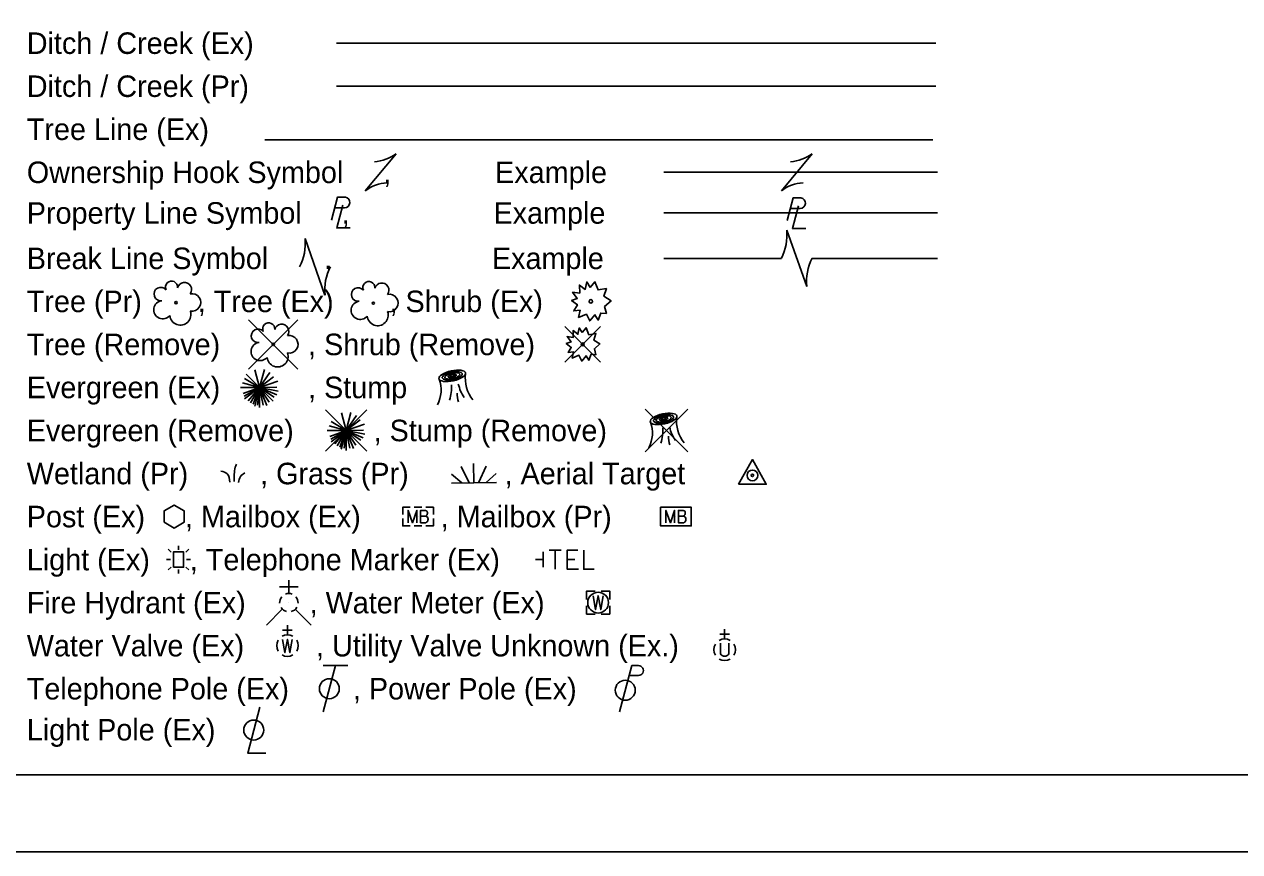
# Model space of a CAD drawing. Extents: x 0 to 34, y -5.4 to 22.
# Drawn here: x 7.96 to 15.87, y 0 to 5.38 of the extents above; entities that cross this region are included whole.
import ezdxf

# ---------------------------------------------------------------- set-up
doc = ezdxf.new("R2010")
doc.units = 0
for name, color, linetype in [('SH_Border', 7, 'Continuous'), ('SH_Cut_Line', 7, 'Continuous'), ('SH_Text', 7, 'Continuous')]:
    doc.layers.add(name, color=color, linetype=linetype)

msp = doc.modelspace()

# ---------------------------------------------------------------- linework, layer by layer
at = {"layer": 'SH_Border'}
msp.add_lwpolyline([(1.5, 21.5), (33.5, 21.5), (33.5, 0.5), (1.5, 0.5)], close=True, dxfattribs=at)
at = {"layer": 'SH_Cut_Line'}
msp.add_lwpolyline([(0, 0), (34, 0), (34, 22), (0, 22)], close=True, dxfattribs=at)
at = {"layer": 'SH_Text'}
for p, q in [((9.9949, 5.2604), (13.8949, 5.2604)), ((9.9949, 4.9804), (13.8949, 4.9804)), ((9.5272, 4.6304), (13.8772, 4.6304)), ((10.1822, 4.3004), (10.3822, 4.5404)), ((12.8904, 4.3004), (13.0904, 4.5404)), ((10.2822, 4.4204), (10.2822, 4.4204)), ((12.1249, 4.4204), (13.9072, 4.4204)), ((12.9904, 4.4204), (12.9904, 4.4204)), ((9.9825, 4.1894), (10.0473, 4.1894)), ((10.0225, 4.1583), (10.0225, 4.1583)), ((12.1249, 4.1558), (13.9072, 4.1558)), ((12.9481, 4.1853), (13.0129, 4.1853)), ((12.9882, 4.1542), (12.9882, 4.1542)), ((12.9254, 4.0446), (13.0554, 3.6764)), ((9.7898, 3.989), (9.9197, 3.6207)), ((9.8547, 3.8049), (9.8547, 3.8049)), ((12.1249, 3.8604), (12.8905, 3.8604)), ((12.9904, 3.8605), (12.9904, 3.8605)), ((13.0903, 3.8604), (13.9072, 3.8604)), ((9.4226, 3.4607), (9.7433, 3.14)), ((9.7433, 3.4607), (9.4226, 3.14)), ((11.4817, 3.4163), (11.7134, 3.1846)), ((11.7134, 3.4163), (11.4817, 3.1846)), ((9.5829, 3.3004), (9.5829, 3.3004)), ((11.5975, 3.3004), (11.5975, 3.3004)), ((9.4934, 3.0202), (9.4062, 3.1074)), ((9.4934, 3.0202), (9.4626, 3.1355)), ((9.4934, 3.0202), (9.5249, 3.1377)), ((9.4934, 3.0202), (9.5598, 3.1173)), ((9.4934, 3.0202), (9.5849, 3.0903)), ((9.3701, 3.0202), (9.4934, 3.0202)), ((9.4934, 3.0202), (9.3831, 3.0498)), ((9.4934, 3.0202), (9.3862, 2.9812)), ((9.4934, 3.0202), (9.3939, 2.9632)), ((9.4934, 3.0202), (9.3958, 3.0776)), ((9.4934, 3.0202), (9.3958, 2.9453)), ((9.4934, 3.0202), (9.4198, 2.9335)), ((9.4934, 3.0202), (9.4355, 2.9198)), ((9.4934, 3.0202), (9.4518, 2.9117)), ((9.4934, 3.0202), (9.4619, 2.8988)), ((9.4934, 3.0202), (9.4799, 2.9054)), ((9.4934, 3.0202), (9.6119, 3.0604)), ((9.4934, 3.0202), (9.6062, 3.0225)), ((9.4934, 2.8892), (9.4934, 3.0202)), ((9.4934, 3.0202), (9.5165, 2.9043)), ((9.4934, 3.0202), (9.5418, 2.9035)), ((9.4934, 3.0202), (9.5569, 2.9254)), ((9.4934, 3.0202), (9.5831, 2.9322)), ((9.4934, 3.0202), (9.589, 2.9563)), ((9.4934, 3.0202), (9.6051, 2.9717)), ((9.4934, 3.0202), (9.6141, 2.9962)), ((10.7671, 3.0204), (10.7671, 3.0204)), ((9.9238, 2.8741), (10.1911, 2.6068)), ((10.1911, 2.8741), (9.9238, 2.6068)), ((10.0575, 2.7404), (10.0266, 2.8558)), ((10.0575, 2.7404), (10.0889, 2.8579)), ((12.0036, 2.8795), (12.2817, 2.6014)), ((12.2817, 2.8795), (12.0036, 2.6014)), ((10.0575, 2.7404), (9.9471, 2.77)), ((10.0575, 2.7404), (9.9598, 2.7978)), ((10.0575, 2.7404), (9.9702, 2.8276)), ((10.0575, 2.7404), (10.1238, 2.8376)), ((10.0575, 2.7404), (10.1489, 2.8106)), ((10.0575, 2.7404), (10.1759, 2.7806)), ((9.9341, 2.7404), (10.0575, 2.7404)), ((10.0575, 2.7404), (9.9502, 2.7014)), ((10.0575, 2.7404), (9.9579, 2.6834)), ((10.0575, 2.7404), (9.9598, 2.6656)), ((10.0575, 2.7404), (9.9838, 2.6538)), ((10.0575, 2.7404), (9.9995, 2.6401)), ((10.0575, 2.7404), (10.0158, 2.6319)), ((10.0575, 2.7404), (10.0259, 2.619)), ((10.0575, 2.7404), (10.0439, 2.6256)), ((10.0575, 2.7404), (10.1702, 2.7427)), ((10.0575, 2.6094), (10.0575, 2.7404)), ((10.0575, 2.7404), (10.0805, 2.6245)), ((10.0575, 2.7404), (10.1058, 2.6237)), ((10.0575, 2.7404), (10.1209, 2.6456)), ((10.0575, 2.7404), (10.1472, 2.6524)), ((10.0575, 2.7404), (10.153, 2.6766)), ((10.0575, 2.7404), (10.1691, 2.6919)), ((10.0575, 2.7404), (10.1782, 2.7165)), ((10.0575, 2.7404), (10.0575, 2.7404)), ((12.1427, 2.7404), (12.1427, 2.7404)), ((12.1427, 2.7404), (12.1427, 2.7404)), ((10.8104, 2.3993), (10.7421, 2.4564)), ((10.8591, 2.4), (10.807, 2.5061)), ((10.8891, 2.4004), (10.8872, 2.5259)), ((10.919, 2.4009), (10.968, 2.5084)), ((10.9678, 2.4016), (11.0343, 2.4607)), ((10.7429, 2.3983), (11.0351, 2.4026)), ((10.5002, 2.2415), (10.5503, 2.2415)), ((10.5258, 2.1804), (10.5258, 2.1804)), ((12.2039, 2.1804), (12.2039, 2.1804)), ((10.5002, 2.1193), (10.5503, 2.1193)), ((8.9662, 1.9644), (8.9662, 1.991)), ((8.914, 1.9008), (8.8874, 1.9008)), ((8.9179, 1.9488), (8.8994, 1.9676)), ((8.9662, 1.9004), (8.9662, 1.9004)), ((9.0328, 1.9676), (9.0142, 1.9488)), ((9.0449, 1.9008), (9.0182, 1.9008)), ((11.3388, 1.9004), (11.289, 1.9004)), ((11.3388, 1.8504), (11.3388, 1.9504)), ((8.9179, 1.852), (8.8994, 1.8333)), ((8.9662, 1.8364), (8.9662, 1.8098)), ((9.0328, 1.8333), (9.0142, 1.852)), ((9.6842, 1.6806), (9.6842, 1.7666)), ((9.7442, 1.7236), (9.6242, 1.7236)), ((9.6843, 1.6204), (9.6843, 1.6204)), ((9.6843, 1.6204), (9.6843, 1.6204)), ((11.6978, 1.6204), (11.6978, 1.6204)), ((9.6419, 1.578), (9.5379, 1.4741)), ((9.7265, 1.578), (9.8305, 1.4741)), ((9.7069, 1.4423), (9.6433, 1.4423)), ((9.6751, 1.4104), (9.6751, 1.474)), ((12.5213, 1.384), (12.5213, 1.4475)), ((12.553, 1.4158), (12.4894, 1.4158)), ((12.4941, 1.3571), (12.4941, 1.2882)), ((12.5484, 1.3571), (12.5484, 1.2882)), ((9.6751, 1.3404), (9.6751, 1.3404)), ((12.5213, 1.314), (12.5213, 1.314)), ((9.9881, 1.2104), (9.9078, 0.9104)), ((10.0681, 1.2104), (9.9081, 1.2104)), ((11.9171, 1.2104), (11.8368, 0.9104)), ((11.9171, 1.2104), (11.9596, 1.2104)), ((11.9, 1.1467), (11.9596, 1.1467))]:
    msp.add_line(p, q, dxfattribs=at)
for points in [[(9.9615, 4.1098), (10.0005, 4.2581), (10.0522, 4.258)], [(10.0359, 4.2063), (9.9963, 4.0584), (10.0836, 4.0584)], [(12.9271, 4.1058), (12.9662, 4.254), (13.0178, 4.2539)], [(13.0015, 4.2022), (12.9619, 4.0543), (13.0493, 4.0543)], [(11.6463, 3.6709), (11.6765, 3.7077), (11.6973, 3.655), (11.7519, 3.664), (11.735, 3.6134), (11.7822, 3.5837), (11.7394, 3.5469), (11.7519, 3.5013), (11.7142, 3.5047), (11.698, 3.459), (11.6765, 3.4936), (11.6426, 3.4528), (11.6212, 3.4971), (11.5702, 3.4756), (11.5798, 3.5227), (11.5392, 3.5185), (11.5629, 3.558), (11.5245, 3.5864), (11.5614, 3.5996), (11.531, 3.6398), (11.5776, 3.6343), (11.5761, 3.6862), (11.6138, 3.6578), (11.6241, 3.707), (11.6463, 3.6709)], [(11.594, 3.3774), (11.6197, 3.4086), (11.6373, 3.3638), (11.6837, 3.3715), (11.6693, 3.3285), (11.7095, 3.3032), (11.6731, 3.272), (11.6837, 3.2331), (11.6517, 3.236), (11.6379, 3.1972), (11.6197, 3.2266), (11.5908, 3.1919), (11.5726, 3.2296), (11.5293, 3.2113), (11.5374, 3.2513), (11.5029, 3.2478), (11.5231, 3.2814), (11.4904, 3.3055), (11.5218, 3.3167), (11.496, 3.3509), (11.5356, 3.3462), (11.5343, 3.3903), (11.5663, 3.3662), (11.5751, 3.408), (11.594, 3.3774)], [(8.8729, 2.1429), (8.9379, 2.1054), (9.0028, 2.1429), (9.0028, 2.2179), (8.9379, 2.2554), (8.8729, 2.2179), (8.8729, 2.1429)], [(10.4258, 2.193), (10.4258, 2.2415), (10.4743, 2.2415)], [(10.461, 2.1404), (10.461, 2.2204), (10.49, 2.1404), (10.5177, 2.2204), (10.5177, 2.1404)], [(10.5769, 2.1839), (10.58, 2.187), (10.5819, 2.1889), (10.5832, 2.1908), (10.5838, 2.1921), (10.5851, 2.1946), (10.5857, 2.1965), (10.587, 2.2009), (10.587, 2.2028), (10.587, 2.2053), (10.5863, 2.2091), (10.5851, 2.2122), (10.5832, 2.2148), (10.58, 2.2173), (10.5775, 2.2185), (10.5763, 2.2192), (10.5731, 2.2204), (10.5422, 2.2204), (10.5422, 2.1404), (10.5769, 2.1404), (10.5813, 2.1429), (10.5851, 2.1461), (10.5882, 2.1511), (10.5901, 2.1568), (10.5908, 2.1625), (10.5908, 2.1663), (10.5895, 2.17), (10.587, 2.1757), (10.5838, 2.1795), (10.5769, 2.1839), (10.5422, 2.1839)], [(10.5761, 2.2415), (10.6258, 2.2415), (10.6258, 2.193)], [(12.1391, 2.1404), (12.1391, 2.2204), (12.1681, 2.1404), (12.1958, 2.2204), (12.1958, 2.1404)], [(12.255, 2.1839), (12.2582, 2.187), (12.2601, 2.1889), (12.2613, 2.1908), (12.2619, 2.1921), (12.2632, 2.1946), (12.2638, 2.1965), (12.2651, 2.2009), (12.2651, 2.2028), (12.2651, 2.2053), (12.2645, 2.2091), (12.2632, 2.2122), (12.2613, 2.2148), (12.2582, 2.2173), (12.2556, 2.2185), (12.2544, 2.2192), (12.2512, 2.2204), (12.2204, 2.2204), (12.2204, 2.1404), (12.255, 2.1404), (12.2594, 2.1429), (12.2632, 2.1461), (12.2664, 2.1511), (12.2682, 2.1568), (12.2689, 2.1625), (12.2689, 2.1663), (12.2676, 2.17), (12.2651, 2.1757), (12.2619, 2.1795), (12.255, 2.1839), (12.2204, 2.1839)], [(10.4743, 2.1193), (10.4258, 2.1193), (10.4258, 2.1678)], [(10.6258, 2.1678), (10.6258, 2.1193), (10.5761, 2.1193)], [(11.3796, 1.9625), (11.4574, 1.9625)], [(11.419, 1.9625), (11.419, 1.8375)], [(11.5646, 1.9625), (11.4967, 1.9625), (11.4967, 1.8375), (11.5696, 1.8375)], [(11.4967, 1.9005), (11.545, 1.9005)], [(11.604, 1.9625), (11.604, 1.8375), (11.6719, 1.8375)], [(11.6778, 1.6954), (11.6228, 1.6954), (11.6228, 1.6404)], [(11.6645, 1.6654), (11.6812, 1.5754), (11.6978, 1.6654), (11.7145, 1.5754), (11.7312, 1.6654)], [(11.7728, 1.6404), (11.7728, 1.6954), (11.7178, 1.6954)], [(11.6228, 1.6004), (11.6228, 1.5454), (11.6778, 1.5454)], [(11.7178, 1.5454), (11.7728, 1.5454), (11.7728, 1.6004)], [(9.6433, 1.3814), (9.6592, 1.2953), (9.6751, 1.3814), (9.6911, 1.2953), (9.7069, 1.3814)], [(9.4954, 0.9392), (9.4167, 0.6399), (9.5348, 0.6399)]]:
    msp.add_lwpolyline(points, dxfattribs=at)
for points in [[(12.6121, 2.3904), (12.7921, 2.3904), (12.7021, 2.5514)], [(12.1039, 2.2415), (12.3039, 2.2415), (12.3039, 2.1193), (12.1039, 2.1193)], [(8.9328, 1.8504), (8.9994, 1.8504), (8.9994, 1.9504), (8.9328, 1.9504)]]:
    msp.add_lwpolyline(points, close=True, dxfattribs=at)
for centre, radius in [((8.9499, 3.5723), 0.0084), ((10.2345, 3.5689), 0.0072), ((11.6505, 3.5804), 0.0115), ((9.5829, 3.3004), 0.0072), ((11.5975, 3.3004), 0.00979), ((12.7021, 2.4483), 0.035), ((12.7021, 2.4483), 0.008), ((11.6978, 1.6204), 0.0675), ((9.948, 1.0604), 0.065), ((11.8743, 1.0504), 0.065), ((9.4561, 0.7915), 0.065)]:
    msp.add_circle(centre, radius, dxfattribs=at)
for centre, radius, start, end in [((10.2241, 4.7554), 0.2668, 273.69448, 306.33701), ((12.9323, 4.7554), 0.2668, 273.69448, 306.33701), ((10.3403, 4.0855), 0.2668, 93.69448, 126.33701), ((13.0485, 4.0855), 0.2668, 93.69448, 126.33701), ((10.047, 4.2239), 0.0345, 270.47098, 81.3281), ((13.0126, 4.2198), 0.0345, 270.47098, 81.3281), ((12.5934, 4.0122), 0.3335, 332.94224, 5.58476), ((9.4578, 3.9565), 0.3335, 332.94224, 5.58476), ((10.2517, 3.6532), 0.3335, 152.94224, 185.58476), ((13.3873, 3.7088), 0.3335, 152.94224, 185.58476), ((8.8507, 3.6282), 0.0441, 39.06254, 279.54124), ((8.9204, 3.6733), 0.0395, 354.0047, 205.97412), ((9.0047, 3.6572), 0.0466, 323.82996, 165.0376), ((10.1353, 3.6248), 0.0441, 39.06254, 279.54124), ((10.205, 3.6699), 0.0395, 354.0047, 205.97412), ((10.2893, 3.6537), 0.0466, 323.82996, 165.0376), ((8.8643, 3.5259), 0.0592, 96.17219, 320.57371), ((9.0537, 3.5734), 0.0574, 259.14531, 101.45961), ((10.1489, 3.5224), 0.0592, 96.17219, 320.57371), ((10.3383, 3.5699), 0.0574, 259.14531, 101.45961), ((8.9783, 3.4942), 0.0685, 184.94757, 19.45715), ((10.2629, 3.4907), 0.0685, 184.94757, 19.45715), ((9.5534, 3.4014), 0.0395, 354.0047, 205.97412), ((9.6377, 3.3853), 0.0466, 323.82996, 165.0376), ((9.4837, 3.3563), 0.0441, 39.06254, 279.54124), ((9.6868, 3.3015), 0.0574, 259.14531, 101.45961), ((9.4973, 3.2539), 0.0592, 96.17219, 320.57371), ((9.6113, 3.2222), 0.0685, 184.94757, 19.45715), ((11.0474, 3.0775), 0.2146, 171.41061, 219.91939), ((10.4755, 3.0031), 0.2001, 331.53375, 20.92689), ((10.4912, 3.0217), 0.2527, 340.79377, 3.54808), ((11.0925, 3.1233), 0.316, 194.9653, 212.12159), ((10.9623, 2.9804), 0.1819, 178.79264, 197.12241), ((11.8511, 2.7231), 0.2001, 331.53375, 20.92689), ((12.4229, 2.7975), 0.2146, 171.41061, 219.91939), ((11.8668, 2.7417), 0.2527, 340.79377, 3.54808), ((12.3379, 2.7004), 0.1819, 178.79264, 197.12241), ((12.4681, 2.8433), 0.316, 194.9653, 212.12159), ((9.6843, 1.6204), 0.06, 68.13946, 112.03798), ((9.6843, 1.6204), 0.06, 140.02099, 184.06293), ((9.6843, 1.6204), 0.06, 211.87877, 255.84793), ((9.6843, 1.6204), 0.06, 283.82389, 329.90967), ((9.6843, 1.6204), 0.06, 356.01648, 39.98885), ((9.6751, 1.3405), 0.07, 150.01836, 209.98164), ((9.6751, 1.3405), 0.07, 60.01836, 120.01574), ((9.6751, 1.3405), 0.07, 330.01836, 29.98164), ((12.5212, 1.3141), 0.07, 150.01836, 209.98164), ((12.5212, 1.3141), 0.07, 60.01836, 120.01574), ((12.5212, 1.3141), 0.07, 330.01836, 29.98164), ((9.6751, 1.3405), 0.07, 239.98426, 299.98164), ((12.5212, 1.301), 0.03, 205.19243, 334.80757), ((11.9602, 1.1786), 0.0319, 268.8767, 91.1233), ((12.5212, 1.3141), 0.07, 239.98426, 299.98164)]:
    msp.add_arc(centre, radius, start, end, dxfattribs=at)
for centre, major_axis in [((10.7483, 3.096), (0.0868, 0.0187)), ((10.7483, 3.096), (0.0651, 0.0141)), ((10.7483, 3.096), (0.0488, 0.0105)), ((10.7483, 3.096), (0.0275, 0.0059)), ((10.7483, 3.096), (0.0154, 0.0033)), ((12.1239, 2.816), (0.0868, 0.0187)), ((12.1239, 2.816), (0.0651, 0.0141)), ((12.1239, 2.816), (0.0488, 0.0105)), ((12.1239, 2.816), (0.0275, 0.0059)), ((12.1239, 2.816), (0.0154, 0.0033))]:
    msp.add_ellipse(centre, major_axis=major_axis, ratio=0.36865, dxfattribs=at)
for points in [[(9.2422, 2.476), (9.2836, 2.4583), (9.3013, 2.405)], [(9.3295, 2.409), (9.3295, 2.4563), (9.3354, 2.5007), (9.3443, 2.5215)], [(9.3573, 2.4018), (9.3691, 2.4402), (9.3986, 2.464)]]:
    msp.add_spline(points, degree=3, dxfattribs=at)

# ---------------------------------------------------------------- texts
for s, p in [('Ditch / Creek (Ex)', (7.9786, 5.1904)), ('Ditch / Creek (Pr)', (7.9786, 4.9104)), ('Tree Line (Ex)', (7.9786, 4.6304)), ('Ownership Hook Symbol     ,             Example', (7.9786, 4.3504)), ('Property Line Symbol     ,                  Example', (7.9786, 4.0858)), ('Break Line Symbol       ,                    Example', (7.9786, 3.7904)), ('Tree (Pr)       , Tree (Ex)       , Shrub (Ex)', (7.9786, 3.5104)), ('Tree (Remove)           , Shrub (Remove)', (7.9786, 3.2304)), ('Evergreen (Ex)           , Stump ', (7.9786, 2.9504)), ('Evergreen (Remove)          , Stump (Remove)', (7.9786, 2.6704)), ('Wetland (Pr)         , Grass (Pr)            , Aerial Target    ', (7.9786, 2.3904)), ('Post (Ex)     , Mailbox (Ex)          , Mailbox (Pr)', (7.9786, 2.1104)), ('Light (Ex)     , Telephone Marker (Ex)     ', (7.9786, 1.8304)), ('Fire Hydrant (Ex)        , Water Meter (Ex)', (7.9786, 1.5504)), ('Water Valve (Ex)         , Utility Valve Unknown (Ex.)', (7.9786, 1.2704)), ('Telephone Pole (Ex)        , Power Pole (Ex)', (7.9786, 0.9904)), ('Light Pole (Ex)     ', (7.9786, 0.7234))]:
    msp.add_text(s, height=0.14, dxfattribs=at).set_placement(p)

doc.saveas('drawing.dxf')
